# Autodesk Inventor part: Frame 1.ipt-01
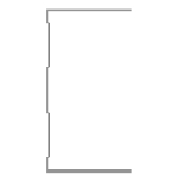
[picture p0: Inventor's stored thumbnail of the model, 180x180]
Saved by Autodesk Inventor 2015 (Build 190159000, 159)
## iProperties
_CCFamilyMember: 1
_CCFamilyDisplayName: Kévin - Kévin Novo
_FrameMemberDoc: Frame Member File
_Version: 15.0.0
_GetPNFromCC: 1
Created: 2015-04
Part Number: Frame 1.ipt-01
Material: Aluminum 6061
Description: Kévin Novo
Document SubType Name: Modeling
Standard: Kevin
Designer: suporte
Standards Organization: Kevin
Language: en-US
Size Designation: (Unnamed 1)
Categories: <MemberInstance><Categories><Category DisplayName="Structural Shapes" InternalName="089c4875-fa83-4c05-b084-43b9cc11f5ed" Mnemonic="GRDR"><CategoryParameter Dis
Density: 2.7 g/cm^3
Appearance: Aluminum - Flat
IsCustomPart: 1
G_L: 1700,000 mm
G_W: 50,000 mm
G_H: 75,000 mm
+ECB053AE-5BFE-4DAF-A828-542376D77D29+CUTDETAIL1: Cut
Author: suporte
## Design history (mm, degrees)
node "Start Plane"
node "End Plane"
sketch "Sketch"
  geometry: L1 (24.7, 37.5)-(24.7, 36.9); L2 (24.7, 36.9)-(-24.7, 36.9); L3 (-24.7, -36.9)-(24.7, -36.9); L4 (24.7, -36.9)-(24.7, -37.5); L5 (24.7, -37.5)-(-25.3, -37.5); L6 (-25.3, 37.5)-(24.7, 37.5); L7 (-24.7, 36.9)-(-24.7, 31.9); L8 (-24.7, 31.9)-(-23.3, 30.5); L9 (-23.3, 30.5)-(-23.3, 10.934); L10 (-23.3, 10.934)-(-24.7, 9.534); L11 (-24.7, 9.534)-(-24.7, -9.534); L12 (-24.7, -9.534)-(-23.3, -10.934); L13 (-23.3, -10.934)-(-23.3, -30.5); L14 (-23.3, -30.5)-(-24.7, -31.9); L15 (-24.7, -31.9)-(-24.7, -36.9); L16 (-25.3, -37.5)-(-25.3, -31.651); L17 (-25.3, -31.651)-(-23.9, -30.251); L18 (-23.9, -30.251)-(-23.9, -11.183); L19 (-23.9, -11.183)-(-25.3, -9.783); L20 (-25.3, -9.783)-(-25.3, 9.783); L21 (-25.3, 9.783)-(-23.9, 11.183); L22 (-23.9, 11.183)-(-23.9, 30.251); L23 (-23.9, 30.251)-(-25.3, 31.651); L24 (-25.3, 31.651)-(-25.3, 37.5); L25 (-25.3, 0)-(30.37, 0); 3 further points
  constraints: 50 end point, 10 point on line, 9 parallel, 5 perpendicular, 4 equal length, 3 midpoint, 3 vertical, 2 vertical alignment, 1 collinear, 1 horizontal, 1 horizontal alignment
  dimensions: "d3" = 0.6 distance of L1.start L1.end (= d6); "d5" = 75 distance between parallel lines of L5 L6; "d6" = 0.6 distance between parallel lines of L24 L7 (= d8); "d7" = 0.6 distance between parallel lines of L8 L23 (= d8); "d8" = 0.6 distance between parallel lines of L22 L9 (= d12); "Espessura" = 0.6 distance between parallel lines of L17 L14; "d10" = 0.6 distance between parallel lines of L13 L18 (= Espessura); "d11" = 0.6 distance between parallel lines of L12 L19 (= Espessura); "d12" = 0.6 distance between parallel lines of L21 L10 (= d11); "d13" = 5 distance of L2.end L7.end; "d15" = 135 deg angle of L9 L8; "d16" = 2 distance between parallel lines of L24 L9; "d17" = 50 distance of L6.start L1.start
extrude "Body" join sketch "Sketch" stored distance "d24" = 0.13; taper "d25" = 0 deg
node "Driven Length"
  sketch "Sketch10"
    geometry: L1 (0, 0)-(10, 0) reference
    constraints: 2 end point, 1 horizontal
  workplane "Work Plane7"
  sketch "Sketch11"
    geometry: L1 (-2, 25)-(12, 25) reference; L2 (-2, 1725)-(12, 1725) reference
    dimensions: "d27" = 1700 distance between parallel lines of L1 L2 (derived)
workplane "Work Plane8"
split "Split1"
body "Solid1"
other parameters: "tamanho" = 1725, "G_OFFSET_START" = -25 [user parameter; used in 1 equation term], "G_OFFSET_END" = 0 [user parameter; used in 1 equation term], "d22" = 25 (= -G_OFFSET_START), "d23" = 1725 (= tamanho + G_OFFSET_END), "G_L" = 1700 (= d27) [user parameter], "d34" = 90 deg
